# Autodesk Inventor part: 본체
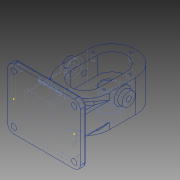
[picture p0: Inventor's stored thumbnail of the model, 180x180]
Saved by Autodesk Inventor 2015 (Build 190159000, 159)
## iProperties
Created: 2020-09
Part Number: 본체
Material: 알루미늄 6061
Document SubType Name: Modeling
Designer: Administrator
Density: 2.7 g/cm^3
Appearance: 알루미늄 - 평지
Mass: 1441.45 g
Surface Area: 790.188 cm^2
Volume: 533.871 cm^3
Author: Administrator
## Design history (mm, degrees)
sketch "스케치1"
  geometry: L1 (-60, 50)-(60, 50); L2 (60, 50)-(60, -50); L3 (60, -50)-(-60, -50); L4 (-60, -50)-(-60, 50); L5 (-60, 50)-(60, -50); L6 (60, 50)-(-60, -50); 1 further point
  constraints: 12 end point, 2 midpoint, 2 parallel, 1 horizontal, 1 perpendicular
  dimensions: "d0" = 120 distance of L2.end L3.end; "d1" = 100 distance of L1.end L2.end
extrude "돌출1" new body sketch "스케치1" distance "d2" = 10; taper "d3" = 0 deg
fillet "모깎기1" dims "d4" = 10
node "작업 평면1"
sketch "스케치3"
  geometry: L1 (0, -25)-(0, 12); L2 (106.75, -50)-(120.75, -50); L3 (152, -33)-(152, 20); L4 (152, 20)-(90, 20); L5 (0, 12)-(28, 12); L6 (28, 12)-(28, -25); L7 (28, -25)-(0, -25); L8 (90, 20)-(136, 20); L9 (136, 20)-(136, -9); L10 (136, -9)-(119.25, -9); L11 (119.25, -9)-(119.25, -24); L12 (119.25, -9)-(106.75, -9); L13 (106.75, -9)-(106.75, -24); L14 (90, 20)-(90, -9); L15 (90, -9)-(106.75, -9); L16 (119.25, -24)-(115.25, -24); L17 (115.25, -24)-(115.25, -42); L18 (115.25, -42)-(120.75, -42); L19 (120.75, -42)-(120.75, -50); L20 (106.75, -24)-(106.75, -50); L21 (115.25, -24)-(106.75, -24); L22 (115.25, -42)-(106.75, -42); L23 (106.75, -50)-(125.75, -50); L24 (125.75, -50)-(125.75, -33); L25 (125.75, -33)-(152, -33); L26 (106.75, -50)-(87.75, -50); L27 (87.75, -50)-(87.75, -33); L28 (87.75, -33)-(28, -33); L29 (28, -33)-(28, -25); L30 (90, 20)-(28, 20); L31 (28, 20)-(28, 12); L32 (125.75, -33)-(106.75, -33); L33 (90, -9)-(73.25, -9); L34 (73.25, -9)-(73.25, -24); L35 (73.25, -9)-(60.75, -9); L36 (60.75, -9)-(60.75, -24); L37 (60.75, -24)-(73.25, -24); 2 further points
  constraints: 74 end point, 17 perpendicular, 12 horizontal, 5 point on line, 3 vertical, 2 parallel
  dimensions: "d13" = 37 distance of L1.start L1.end; "d16" = 53 distance of L3.start L3.end; "d17" = 62 distance of L3.end L4.end; "d19" = 46 distance of L4.end L8.end; "d20" = 29 distance of L8.end L9.end; "d21" = 16.75 distance of L9.end L10.end; "d22" = 15 distance of L10.end L11.end; "d23" = 12.5 distance of L10.end L12.end; "d24" = 4 distance of L11.end L16.end; "d26" = 5.5 distance of L17.end L18.end; "d27" = 19 distance of L2.start L23.end; "d28" = 17 distance of L23.end L24.end; "d29" = 19 distance of L2.start L26.end; "d30" = 17 distance of L26.end L27.end; "d31" = 62 distance of L4.end L30.end; "d52" = 16.75 distance of L14.end L33.end; "d53" = 15 distance of L33.end L34.end; "d54" = 12.5 distance of L33.end L35.end; "d57" = 152 distance between parallel lines of L1 L3; "d58" = 9 distance between parallel lines of L18 L25; "d59" = 45 distance between parallel lines of L5 L25; "d60" = 152 distance from line of point (0, 0) L3; "d61" = 33 distance from line of point (0, 0) L25
node "작업 평면2"
sketch "스케치4"
  geometry: L1 (0, 0)-(0, 90); L2 (0, 90)-(0, 112); L3 (0, 90)-(0, 68); L4 (-40, 112)-(-40, 68); L5 (40, 112)-(40, 68); A1 r 40 centre (0, 112) between (40, 112) and (-40, 112); A2 r 40 centre (0, 68) between (-40, 68) and (40, 68)
  constraints: 10 end point, 4 point on circle, 3 vertical, 2 centre point, 2 coincident, 2 tangent, 1 parallel, 1 point on line
  dimensions: "d33" = 90 distance of L1.start L1.end; "d34" = 22 distance of L2.end L1.end; "d35" = 40 radius of A1; "d36" = 22 distance of L1.end L3.end; "d37" = 40 radius of A2
extrude "돌출3" join sketch "스케치4" distance "d38" = 53; taper "d39" = 0 deg
sketch "스케치5"
  geometry: L1 (-24, 112)-(-24, 68); L2 (24, 68)-(24, 112); A1 r 40 centre (0, 68) between (-40, 68) and (40, 68) reference; A2 r 24 centre (0, 68) between (-24, 68) and (24, 68); A3 r 40 centre (0, 112) between (40, 112) and (-40, 112) reference; A4 r 24 centre (0, 112) between (24, 112) and (-24, 112); 1 further point
  constraints: 4 end point, 4 point on circle, 2 centre point, 2 coincident, 2 tangent, 1 parallel, 1 vertical
  dimensions: "d40" = 24 radius of A2; "d42" = 24 radius of A4
extrude "돌출4" cut sketch "스케치5" distance "d43" = 29; taper "d44" = 0 deg
node "작업 평면3"
sketch "스케치6"
  geometry: L1 (0, 152)-(0, 125.75); L2 (0, 125.75)-(0, 106.75); C1 r 19 at (0, 106.75); A1 r 40 centre (0, 112) between (40, 112) and (-40, 112) reference; 1 further point
  constraints: 4 end point, 2 vertical, 1 centre point, 1 coincident, 1 point on circle
  dimensions: "d46" = 26.25 distance of L1.start L1.end; "d47" = 19 distance of L1.end L2.end; "d48" = 19 radius of C1
extrude "돌출5" join sketch "스케치6" distance "d49" = 17; taper "d50" = 0 deg
revolve "회전1" stored, may be unused: angle "d51" = 90 deg
node "작업 평면4"
sketch "스케치7"
  geometry: L1 (60.75, -9)-(60.75, -24) reference; L2 (60.75, -24)-(73.25, -24) reference; L3 (60.75, -9)-(60.75, -24); L4 (73.25, -24)-(60.75, -24); L5 (73.25, -24)-(73.25, -9); L6 (73.25, -9)-(60.75, -9); 1 further point
  constraints: 8 end point, 2 perpendicular, 1 collinear, 1 vertical
revolve "회전2" stored, may be unused: angle "d56" = 90 deg
sketch "스케치8"
  geometry: L1 (40, -20)-(40, 33) reference; L2 (-40, -20)-(-40, 33) reference; L3 (24, 9)-(-24, 9) reference; L4 (40, -12)-(40, 25); L5 (40, 25)-(-40, 25); L6 (-40, 25)-(-40, -12); L7 (-40, -12)-(40, -12); 1 further point
  constraints: 8 end point, 4 point on line, 1 parallel, 1 perpendicular
  dimensions: "d65" = 16 distance between parallel lines of L5 L3; "d66" = 21 distance between parallel lines of L7 L3
extrude "돌출6" join sketch "스케치8" distance "d67" = 75.75; taper "d68" = 0 deg
revolve "회전3" stored, may be unused: angle "d69" = 90 deg
sketch "스케치9"
  geometry: L1 (-24, 17.75)-(24, 17.75); L2 (-24, 17.75)-(24, 17.75) reference; L3 (24, 17.75)-(24, 0); L4 (24, 44)-(24, 0) reference; L5 (-24, 0)-(-24, 17.75); A1 r 24 centre (0, 0) between (-24, 0) and (24, 0); 1 further point
  constraints: 6 end point, 2 collinear, 2 point on circle, 2 tangent, 1 centre point, 1 parallel
extrude "돌출7" cut sketch "스케치9" distance "d70" = 21; taper "d71" = 0 deg
sketch "스케치10"
  geometry: L1 (0, 152)-(0, 143); L2 (0, 28)-(0, 37); L3 (-40, 68)-(-40, 112) reference; L4 (-31, 90)-(-31, 112); L5 (-31, 90)-(-31, 68); L6 (40, 68)-(40, 112) reference; L7 (31, 90)-(31, 112); L8 (31, 90)-(31, 68); A1 r 40 centre (0, 112) between (40, 112) and (-40, 112) reference; A2 r 40 centre (0, 68) between (-40, 68) and (40, 68) reference; 1 further point
  constraints: 12 end point, 4 vertical, 2 point on circle
  dimensions: "d72" = 9 distance of L1.start L1.end; "d73" = 9 distance of L2.start L2.end; "d75" = 22 distance of L4.start L4.end; "d76" = 22 distance of L4.start L5.end; "d78" = 22 distance of L7.start L7.end; "d79" = 22 distance of L7.start L8.end; "d80" = 9 distance between parallel lines of L6 L8; "d81" = 40 distance between parallel lines of L6 L1; "d82" = 40 distance between parallel lines of L6 L2; "d83" = 71 distance between parallel lines of L6 L5; "d84" = 9 distance from line of L6.end L7; "d85" = 71 distance from line of L6.end L4; "d86" = 9 distance of L6.end L7.end; "d87" = 71 distance of L6.end L4.end
hole "구멍1" sketch "스케치10" at (0, 143), (-31, 112), (-31, 68), (0, 37), (31, 68), (31, 112) diameter "d88" = 4.134; stored, may be unused: countersink angle "d92" = 90 deg, drill point angle "d94" = 118 deg; dims "d89" = 10, "d90" = 4, "d91" = 2, "d93" = 12
sketch "스케치11"
  geometry: L1 (-60, 40)-(-60, -40) reference; L2 (40, -12)-(-40, -12) reference; L3 (-40, -12)-(-40, 25) reference; L4 (-40, 25)-(40, 25) reference; L5 (40, 25)-(40, -12) reference; L6 (50, 50)-(-50, 50) reference; L7 (-60, 40)-(-60, -40) reference; L8 (-50, -50)-(50, -50) reference; L9 (60, -40)-(60, 40) reference; C1 r 4.5 at (-50, -40); C2 r 4.5 at (-50, 40); C3 r 4.5 at (50, 40); C4 r 4.5 at (50, -40); A1 r 10 centre (-50, -40) between (-60, -40) and (-50, -50) reference; A2 r 10 centre (50, 40) between (60, 40) and (50, 50) reference; A3 r 10 centre (-50, 40) between (-50, 50) and (-60, 40) reference; A4 r 10 centre (-50, -40) between (-60, -40) and (-50, -50) reference; A5 r 10 centre (50, -40) between (50, -50) and (60, -40) reference; 1 further point
  constraints: 4 centre point, 1 coincident
  dimensions: "d99" = 4.5 radius of C1; "d100" = 4.5 radius of C2; "d101" = 4.5 radius of C3; "d102" = 4.5 radius of C4
extrude "돌출8" cut sketch "스케치11" distance "d103" = 21; taper "d104" = 0 deg
fillet "모깎기2" dims "d105" = 3
chamfer "모따기1" distance "d106" = 1; stored, may be unused: second distance "d107" = 2, angle "d108" = 45 deg
node "작업 평면5"
sketch "스케치12"
  geometry: L1 (40, 112)-(40, 68) reference; L2 (40, 90)-(50, 90); L3 (50, 90)-(50, 101); L4 (50, 101)-(40, 101); L5 (-40, 112)-(-40, 68) reference; L6 (-40, 90)-(-50, 90); L7 (-50, 90)-(-50, 101); L8 (-50, 101)-(-40, 101); 1 further point
  constraints: 12 end point, 4 perpendicular, 2 horizontal, 2 midpoint, 2 point on line
  dimensions: "d110" = 10 distance of L2.start L2.end; "d111" = 11 distance of L2.end L3.end; "d112" = 10 distance of L6.start L6.end; "d113" = 11 distance of L6.end L7.end
revolve "회전4" sketch "스케치12" stored, may be unused: angle "d114" = 90 deg
fillet "모깎기3" dims "d115" = 3
sketch "스케치13"
  geometry: 1 further point
hole "구멍2" diameter "d118" = 8.376; stored, may be unused: countersink angle "d122" = 90 deg, drill point angle "d124" = 118 deg; dims "d119" = 30, "d120" = 4, "d121" = 2, "d123" = 37.3, "d136" = 10, "d137" = 10
sketch "스케치14"
  geometry: 1 further point
hole "구멍3" diameter "d127" = 8.376; stored, may be unused: countersink angle "d131" = 90 deg, drill point angle "d133" = 118 deg; dims "d128" = 30, "d129" = 4, "d130" = 2, "d132" = 37.3, "d138" = 10, "d139" = 10
chamfer "모따기2" distance "d134" = 0.7; stored, may be unused: second distance "d135" = 2, angle "d140" = 45 deg
sketch "스케치15"
  geometry: L1 (-60, 40)-(-60, -40) reference; L2 (-50, -50)-(50, -50) reference; A1 r 10 centre (-50, -40) between (-60, -40) and (-50, -50) reference; 2 further points
  constraints: 1 other
  dimensions: "d141" = 60 distance from line of L1 point (0, -38); "d142" = 12 distance from line of L2 point (0, -38)
feature "엠보싱1" sketch "스케치15" dims "d143" = 0.5, "d144" = 0
fillet "모깎기4" dims "d145" = 0.5
node "솔리드1"
node "투영된 루프2"
other parameters: "d11" = 0, "d45" = -33, "d55" = 0, "d109" = 5
